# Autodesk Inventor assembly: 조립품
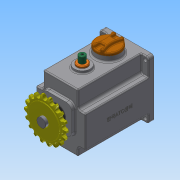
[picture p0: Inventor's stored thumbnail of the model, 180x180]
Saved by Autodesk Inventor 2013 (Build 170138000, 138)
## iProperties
Created: 2017-12
Part Number: 조립품
Document SubType Name: Assembly
Designer: Administrator
Mass: 2741.17 g
Surface Area: 2015.58 cm^2
Volume: 734.131 cm^3
Density: 3.7339 g/cm^3
Author: Administrator
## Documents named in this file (17)
- C:\Users\Administrator\Desktop\371207V1025\조립품.iam
- C:\Users\Administrator\Desktop\371207V1025\본체.ipt
- C:\Users\Administrator\Desktop\371207V1025\커버.ipt
- C:\Users\Administrator\Desktop\371207V1025\메인축.ipt
- C:\Users\Administrator\Desktop\371207V1025\서브축.ipt
- C:\Users\Administrator\Desktop\371207V1025\볼트 M4 x 10.ipt
- C:\Users\Administrator\Desktop\371207V1025\베어링 6003.ipt
- C:\Users\Administrator\Desktop\371207V1025\베어링 608.ipt
- C:\Users\Administrator\Desktop\371207V1025\부시.ipt
- C:\Users\Administrator\Desktop\371207V1025\슬라이더.ipt
- C:\Users\Administrator\Desktop\371207V1025\스프로킷.ipt
- C:\Users\Administrator\Desktop\371207V1025\키 5 x 5 x 18.ipt
- C:\Users\Administrator\Desktop\371207V1025\멈춤나사 M3x8.ipt
- C:\Users\Administrator\Desktop\371207V1025\상부 캡.ipt
- C:\Users\Administrator\Desktop\371207V1025\가변스프링.ipt
- C:\Users\Administrator\Desktop\371207V1025\오일 실 17 32 8.ipt
- C:\Users\Administrator\Desktop\371207V1025\오일 실 8 22 7.ipt
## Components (1 placed, 1 different names)
1. 가변스프링:1
